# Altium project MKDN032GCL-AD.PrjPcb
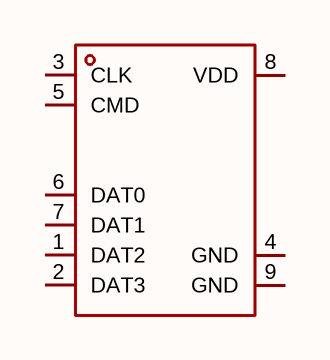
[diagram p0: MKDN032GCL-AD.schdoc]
1 sheet, 1 parts. Net scope: global (net labels, ports and power ports of the same name join across sheets).

## Sheet MKDN032GCL-AD.schdoc
size 127 x 101 mm

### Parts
U?  mkdn032gcl-ad  [LGA-16_L12.5-W9.0-P1.27-TL-EP]  (value not drawn)

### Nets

Not connected (* = marked no-connect by the designer): U? 1(DAT2) 2(DAT3) 3(CLK) 4(GND) 5(CMD) 6(DAT0) 7(DAT1) 8(VDD) 9(GND)

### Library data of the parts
U? = mkdn032gcl-ad: 存储容量:32Gbit;时钟频率(fc):208MHz;工作电压:2.7V~3.6V;; Manufacturer: MK(米客方德); AddInBom: yes; ModelId: aae4acadbbb4480ebd429fe2f08c27d7; ModelTransform: 492.125,354.33,0,0,0,0,0,0,0; Memory Size: 32Gbit; Interface: SD接口; Clock Frequency: 208MHz; Standby Supply Current: 80uA; ECC: 有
